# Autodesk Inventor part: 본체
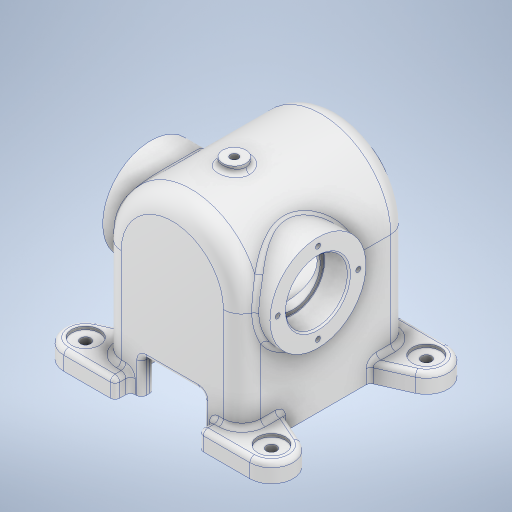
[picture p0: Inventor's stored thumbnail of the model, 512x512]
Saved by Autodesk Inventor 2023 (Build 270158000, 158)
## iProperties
Created: 2024-09
Part Number: 본체
Material: 알루미늄 6061
Document SubType Name: Modeling
Designer: asung
Density: 2.7 g/cm^3
Appearance: 알루미늄 - 평지
Mass: 1380.46 g
Surface Area: 1145.88 cm^2
Volume: 511.281 cm^3
Author: asung
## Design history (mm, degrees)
sketch "스케치1" dims "d0" = 90
  geometry: L1 (-45, 0)-(45, 0); L2 (45, 0)-(45, -76); L3 (45, -76)-(-45, -76); L4 (-45, -76)-(-45, 0); L5 (-20, -76)-(20, -76); L6 (20, -76)-(20, -53); L7 (20, -53)-(-20, -53); L8 (-20, -53)-(-20, -76); 5 further points
  constraints: 16 end point, 4 parallel, 2 horizontal, 2 midpoint, 2 perpendicular, 1 coincident, 1 point on line, 1 vertical, 3 other
  dimensions: "d1" = 90 distance of L2.end L3.end; "d2" = 76 distance of L1.end L2.end; "d3" = 40 distance of L7.end L6.end; "d4" = 23 distance of L6.end L5.end
extrude "돌출1" new body sketch "스케치1" stored distance "d5" = 108; taper "d6" = 0 deg
sketch "스케치2"
  geometry: C1 r 28.5 at (0, 0); 1 further point
  constraints: 1 centre point, 1 coincident
  dimensions: "d7" = 57 diameter of C1
extrude "돌출2" join sketch "스케치2" distance "d8" = 6; taper "d9" = 0 deg
fillet "모깎기1" dims "d10" = 12
fillet "모깎기2" dims "d11" = 3
node "작업 평면1"
sketch "스케치3"
  geometry: L1 (12, 109)-(12, 23) reference; L2 (12, 23)-(-96, 23) reference; L3 (-96, 23)-(-96, 44.5) reference; L4 (-99, 47.5)-(-102, 47.5) reference; L5 (-102, 47.5)-(-102, 104.5) reference; L6 (-102, 104.5)-(-99, 104.5) reference; L7 (-96, 107.5)-(-96, 109) reference; L8 (-84, 121)-(0, 121) reference; L9 (-102, 76)-(12, 76); L10 (3, 76)-(3, 109); L11 (0, 112)-(-84, 112); L12 (-87, 109)-(-87, 76); A1 r 12 centre (0, 109) between (12, 109) and (0, 121) reference; A2 r 3 centre (-99, 44.5) between (-96, 44.5) and (-99, 47.5) reference; A3 r 3 centre (-99, 107.5) between (-99, 104.5) and (-96, 107.5) reference; A4 r 12 centre (-84, 109) between (-84, 121) and (-96, 109) reference; A5 r 3 centre (0, 109) between (3, 109) and (0, 112); A6 r 3 centre (-84, 109) between (-84, 112) and (-87, 109); 1 further point
  constraints: 8 end point, 4 point on circle, 4 tangent, 3 point on line, 2 centre point, 2 perpendicular, 1 equal radius, 1 horizontal, 1 midpoint, 1 vertical
  dimensions: "d12" = 9 distance between parallel lines of L8 L11; "d13" = 9 distance between parallel lines of L10 L1; "d14" = 9 distance from line of L7.end L12; "d15" = 3 radius of A5
revolve "회전1" sketch "스케치3" stored, may be unused: angle "d16" = 90 deg
sketch "스케치4"
  geometry: C1 r 28.5 at (0, 0) reference; 2 further points
  constraints: 1 coincident
hole "구멍1" sketch "스케치4" at (0, 0) diameter "d17" = 33; stored, may be unused: countersink angle "d21" = 90 deg, drill point angle "d23" = 118 deg; dims "d18" = 7, "d19" = 4, "d20" = 2, "d22" = 25
chamfer "모따기1" distance "d24" = 1; stored, may be unused: second distance "d25" = 2, angle "d26" = 45 deg
node "작업 평면2"
sketch "스케치5"
  geometry: L1 (-102, 104.5)-(-102, 47.5) reference; C1 r 31 at (-28, 76)
  constraints: 1 centre point
  dimensions: "d28" = 62 diameter of C1; "d127" = 74 distance from line of L1 C1.centre
extrude "돌출3" join sketch "스케치5" stored distance "d29" = 10; taper "d30" = 0 deg
sketch "스케치9" dims "d60" = 46
  geometry: 3 further points
  constraints: 2 vertical alignment, 1 coincident, 2 other
hole "구멍5" sketch "스케치9" at (0, 23) diameter "d61" = 3.242; stored, may be unused: countersink angle "d65" = 90 deg, drill point angle "d67" = 118 deg; dims "d62" = 8, "d63" = 4, "d64" = 2, "d66" = 10
node "작업 평면3"
sketch "스케치10"
  geometry: L1 (-48.5, -6)-(8.5, -6) reference; C1 r 7.5 at (-20, 68); 1 further point
  constraints: 1 centre point, 1 vertical alignment
  dimensions: "d72" = 15 diameter of C1; "d73" = 74 distance from line of L1 C1.centre
extrude "돌출4" join sketch "스케치10" stored distance "d74" = 10; taper "d75" = 0 deg
fillet "모깎기4" dims "d76" = 3
node "작업 평면4"
sketch "스케치11"
  geometry: L1 (-54, -27.659)-(-54, 27.659) reference; L2 (-54, 27.659)-(-35.496, 27.659) reference; L3 (45, -27.659)-(45, -76) reference; L4 (45, -76)-(20, -76) reference; L5 (20, -76)-(20, -53) reference; L6 (20, -53)-(-20, -53) reference; L7 (-20, -53)-(-20, -76) reference; L8 (-20, -76)-(-45, -76) reference; L9 (-45, -76)-(-45, -27.659) reference; L10 (-45, -27.659)-(-54, -27.659) reference; L11 (-36, -27)-(-36, -76); L12 (36, -27)-(36, -76); L13 (54, 27.659)-(54, -27.659) reference; L14 (54, -27.659)-(45, -27.659) reference; L15 (35.496, 27.659)-(54, 27.659) reference; C1 r 36 at (0, 0) reference; A1 r 45 centre (0, 0) between (-36, -27) and (36, -27); A2 r 45 centre (0, 0) between (35.496, 27.659) and (-35.496, 27.659) reference; 1 further point
  constraints: 4 end point, 2 perpendicular, 2 point on circle, 2 point on line, 1 centre point, 1 coincident
  dimensions: "d78" = 90 diameter of A1; "d79" = 9 distance between parallel lines of L11 L9; "d80" = 9 distance between parallel lines of L3 L12
extrude "돌출5" cut sketch "스케치11" stored distance "d81" = 91; taper "d82" = 0 deg
fillet "모깎기6" dims "d83" = 3
fillet "모깎기7" dims "d84" = 3
sketch "스케치12" dims "d87" = 28
  geometry: L1 (-41, 10)-(107, 10); L2 (107, 10)-(107, -118); L3 (107, -118)-(-41, -118); L4 (-41, -118)-(-41, 10); L5 (-41, 10)-(107, -118); L6 (107, 10)-(-41, -118); L7 (53, -8.5)-(66, -8.5) reference; L8 (69, -11.5)-(69, -96.5) reference; L9 (66, -99.5)-(53, -99.5) reference; L10 (53, -108)-(53, -99.5) reference; L11 (66, -108)-(53, -108) reference; L12 (78, -96)-(78, -12) reference; L13 (53, 0)-(66, 0) reference; L14 (53, -8.5)-(53, 0) reference; L15 (0, -8.5)-(13, -8.5) reference; L16 (13, -8.5)-(13, 0) reference; L17 (0, 0)-(13, 0) reference; L18 (-12, -12)-(-12, -96) reference; L19 (13, -108)-(0, -108) reference; L20 (13, -108)-(13, -99.5) reference; L21 (13, -99.5)-(0, -99.5) reference; L22 (-3, -96.5)-(-3, -11.5) reference; L23 (98.693, -16.79)-(78, -26); L24 (33, 10)-(33, -118); L25 (-32.693, -16.79)-(-12, -26); L26 (107, -54)-(-41, -54); L27 (98.693, -91.21)-(78, -82); L28 (-32.693, -91.21)-(-12, -82); L29 (13, 0)-(53, 0) reference; L30 (53, -108)-(13, -108) reference; L31 (53, -8.5)-(53, 10); L32 (13, -8.5)-(13, 10.982); L33 (13, -99.5)-(13, -118); L34 (53, -99.5)-(53, -118); A1 r 3 centre (66, -11.5) between (69, -11.5) and (66, -8.5) reference; A2 r 3 centre (66, -96.5) between (66, -99.5) and (69, -96.5) reference; A3 r 12 centre (66, -96) between (66, -108) and (78, -96) reference; A4 r 12 centre (66, -12) between (78, -12) and (66, 0) reference; A5 r 12 centre (0, -12) between (0, 0) and (-12, -12) reference; A6 r 12 centre (0, -96) between (-12, -96) and (0, -108) reference; A7 r 3 centre (0, -96.5) between (-3, -96.5) and (0, -99.5) reference; A8 r 3 centre (0, -11.5) between (0, -8.5) and (-3, -11.5) reference; 17 further points
  constraints: 32 end point, 9 symmetric about line, 6 midpoint, 5 point on line, 3 horizontal, 3 perpendicular, 3 vertical, 2 parallel, 13 other
  dimensions: "d85" = 148 distance of L2.end L3.end; "d86" = 128 distance of L1.end L2.end; "d88" = 14 distance from line of point (93, -4) L1; "d89" = 36 distance from line of L23.end L1
extrude "돌출6" join sketch "스케치12" distance "d90" = 12; taper "d91" = 0 deg
sketch "스케치13"
  geometry: L1 (27, 12)-(40, 12) reference; L2 (40, 12)-(40, 23) reference; L3 (40, 23)-(80, 23) reference; L4 (80, 23)-(80, 12) reference; L5 (80, 12)-(93, 12) reference; L6 (93, 76)-(93, 12) reference; L7 (27, 12)-(27, 76) reference; L8 (15, 12)-(27, 12) reference; L9 (27, 12)-(27, 76) reference; L10 (15.381, 76)-(27, 76) reference; L11 (15, 62.696)-(15, 12) reference; L12 (93, 12)-(105, 12) reference; L13 (105, 12)-(105, 62.696) reference; L14 (104.619, 76)-(93, 76) reference; L15 (93, 76)-(93, 12) reference; L16 (33, 12)-(87, 12); L17 (87, 12)-(87, -13.735); L18 (87, -13.735)-(33, -13.735); L19 (33, -13.735)-(33, 12); A1 r 33 centre (60, 76) between (93, 76) and (27, 76) reference; 4 further points
  constraints: 8 end point, 2 parallel, 1 horizontal, 1 perpendicular, 1 point on line, 2 other
  dimensions: "d92" = 18 distance between parallel lines of L19 L11; "d93" = 18 distance between parallel lines of L17 L13; "d94" = 25.73479 distance between parallel lines of L16 L18
extrude "돌출7" cut sketch "스케치13" distance "d95" = 10; taper "d96" = 0 deg
fillet "모깎기8" dims "d97" = 3
fillet "모깎기10" dims "d99" = 3
fillet "모깎기11" dims "d100" = 3
node "작업 평면6"
  node "작업 평면5"
sketch "스케치14"
  geometry: L1 (-28.5, -60)-(28.5, -60) reference; C1 r 7.5 at (0, 14); 1 further point
  constraints: 1 centre point, 1 vertical alignment
  dimensions: "d102" = 15 diameter of C1; "d103" = 74 distance from line of L1 C1.centre
extrude "돌출8" join sketch "스케치14" stored distance "d104" = 10; taper "d105" = 0 deg
fillet "모깎기12" dims "d106" = 3
sketch "스케치15"
  geometry: C1 r 7.5 at (0, 0) reference; 2 further points
  constraints: 1 coincident
hole "구멍6" sketch "스케치15" at (0, 0) diameter "d107" = 5.1881; stored, may be unused: countersink angle "d111" = 90 deg, drill point angle "d113" = 118 deg; dims "d108" = 200, "d109" = 4, "d110" = 2, "d112" = 16
sketch "스케치16"
  geometry: A1 r 14 centre (93, 104) between (98.693, 91.21) and (93, 118) reference; A2 r 14 centre (-27, 104) between (-27, 118) and (-32.693, 91.21) reference; A3 r 14 centre (-27, 4) between (-32.693, 16.79) and (-27, -10) reference; A4 r 14 centre (93, 4) between (93, -10) and (98.693, 16.79) reference; 5 further points
  constraints: 4 coincident
hole "구멍7" sketch "스케치16" at (93, 104), (-27, 104), (-27, 4), (93, 4) diameter "d114" = 6.6; stored, may be unused: countersink angle "d118" = 90 deg, drill point angle "d120" = 118 deg; dims "d115" = 12, "d116" = 18, "d117" = 2, "d119" = 12
fillet "모깎기13" dims "d121" = 3
sketch "스케치17"
  geometry: L1 (60, -76)-(74, -76) reference; 3 further points
  constraints: 1 vertical alignment, 1 other
  dimensions: "d122" = 35 distance from line of L1 point (0, -41)
feature "엠보싱1" sketch "스케치17" dims "d123" = 0.5, "d124" = 0
fillet "모깎기14" dims "d125" = 3
fillet "모깎기15" dims "d126" = 3
fillet "모깎기16" dims "d128" = 3
sketch "스케치18"
  geometry: C1 r 31 at (0, 0) reference; 2 further points
  constraints: 1 coincident
hole "구멍8" sketch "스케치18" at (0, 0) diameter "d129" = 35; stored, may be unused: countersink angle "d133" = 90 deg, drill point angle "d135" = 118 deg; dims "d130" = 6, "d131" = 40, "d132" = 16, "d134" = 200
sketch "스케치19"
  geometry: C1 r 31 at (0, 0) reference; 2 further points
  constraints: 1 coincident
hole "구멍9" sketch "스케치19" at (0, 0) diameter "d136" = 35; stored, may be unused: countersink angle "d140" = 90 deg, drill point angle "d142" = 118 deg; dims "d137" = 6, "d138" = 40, "d139" = 16, "d141" = 200
chamfer "모따기3" distance "d143" = 1; stored, may be unused: second distance "d144" = 2, angle "d145" = 45 deg
sketch "스케치20" dims "d146" = 52
  geometry: C1 r 31 at (0, 0) reference; 3 further points
  constraints: 2 vertical alignment, 1 coincident, 2 other
hole "구멍10" sketch "스케치20" at (0, 26) diameter "d147" = 3.242; stored, may be unused: countersink angle "d151" = 90 deg, drill point angle "d153" = 118 deg; dims "d148" = 8, "d149" = 40, "d150" = 16, "d152" = 10
fillet "모깎기17" dims "d157" = 0.3
node "솔리드1"
mirror "미러1"
pattern_circular "원형 패턴2" dims angle "d69" = 360 deg
mirror "미러3"
pattern_circular "원형 패턴3" dims angle "d155" = 360 deg
mirror "미러4"
node "투영된 루프1"
node "투영된 루프2"
node "투영된 루프3"
node "투영된 루프4"
node "투영된 루프5"
node "절단 모서리 투영1"
node "절단 모서리 투영2"
feature "A9D066F2-1C7D-4E18-AEED-F7BC21143FA4" dims "d17" = 33, "d18" = 7, "d19" = 4, "d20" = 2, "d21" = 90 deg, "d22" = 25, "d23" = 118 deg
other parameters: "d27" = -54, "d71" = -125, "d101" = -4
